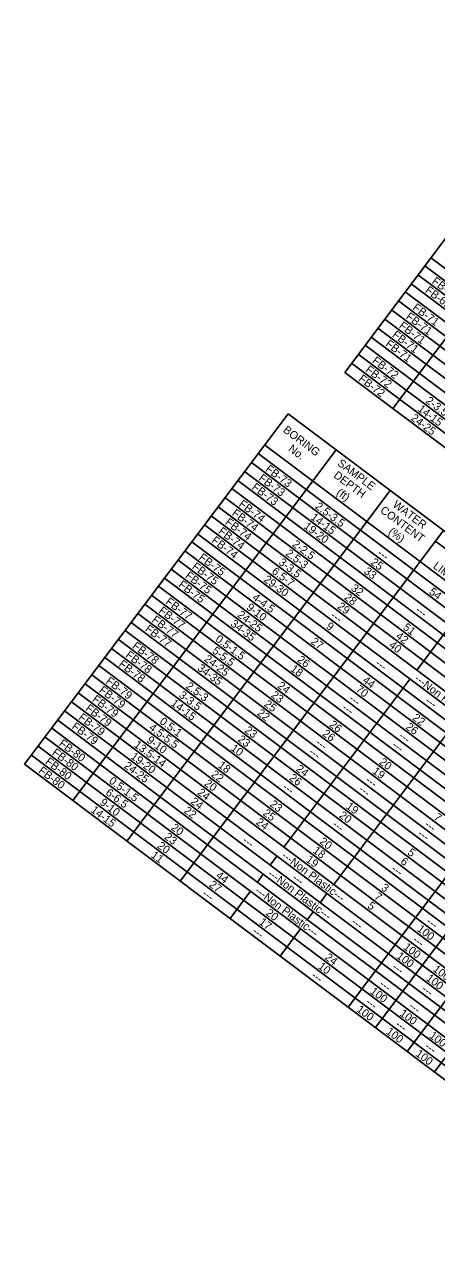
# Model space of a CAD drawing. Extents: x 627484.2 to 627514.4, y 367972.1 to 367996.9.
# Drawn here: x 627505.89 to 627508.72, y 367977.2 to 367985.65 of the extents above; entities that cross this region are included whole.
import ezdxf

# ---------------------------------------------------------------- set-up
doc = ezdxf.new("R2010")
doc.units = 0
doc.layers.add('Default', color=7, linetype='Continuous')
doc.layers.add('R_Survey Control', color=7, linetype='Continuous')

msp = doc.modelspace()

# ---------------------------------------------------------------- linework, layer by layer
at = {"layer": 'Default'}
for p, q in [((627508.0877, 367983.2583), (627509.8821, 367985.648)), ((627508.4191, 367983.0095), (627510.2135, 367985.3992)), ((627508.679, 367984.0458), (627513.1543, 367980.6853)), ((627508.5912, 367983.9289), (627513.0665, 367980.5684)), ((627508.638, 367983.9912), (627513.1133, 367980.6307)), ((627508.5444, 367983.8665), (627513.0196, 367980.506)), ((627508.4566, 367983.7495), (627512.9318, 367980.389)), ((627508.5034, 367983.8119), (627512.9786, 367980.4514)), ((627508.4097, 367983.6872), (627512.885, 367980.3267)), ((627508.3629, 367983.6248), (627512.8381, 367980.2643)), ((627508.2692, 367983.5), (627512.7445, 367980.1395)), ((627508.3161, 367983.5624), (627512.7913, 367980.2019)), ((627508.2282, 367983.4455), (627512.7035, 367980.085)), ((627508.1814, 367983.3831), (627512.6566, 367980.0226)), ((627508.0877, 367983.2583), (627512.563, 367979.8978)), ((627508.1346, 367983.3207), (627512.6098, 367979.9602)), ((627505.8895, 367980.5654), (627507.6986, 367982.9746)), ((627507.6986, 367982.9746), (627512.1738, 367979.6141)), ((627507.5376, 367982.7602), (627512.0128, 367979.3997)), ((627506.2209, 367980.3166), (627508.0299, 367982.7257)), ((627507.4937, 367982.7017), (627511.9689, 367979.3412)), ((627507.4, 367982.5769), (627511.8753, 367979.2164)), ((627507.4468, 367982.6393), (627511.9221, 367979.2788)), ((627507.3532, 367982.5146), (627511.8284, 367979.1541)), ((627506.5912, 367980.0385), (627508.4003, 367982.4477)), ((627507.2654, 367982.3976), (627511.7406, 367979.0371)), ((627507.3122, 367982.46), (627511.7874, 367979.0995)), ((627507.2185, 367982.3352), (627511.6938, 367978.9747)), ((627507.1717, 367982.2729), (627511.6469, 367978.9124)), ((627506.9577, 367979.7633), (627508.7667, 367982.1725)), ((627507.078, 367982.1481), (627511.5533, 367978.7876)), ((627507.1248, 367982.2105), (627511.6001, 367978.85)), ((627507.037, 367982.0936), (627511.5123, 367978.733)), ((627508.7111, 367982.0984), (627509.865, 367981.232)), ((627506.9902, 367982.0312), (627511.4654, 367978.6707)), ((627506.8965, 367981.9064), (627511.3718, 367978.5459)), ((627506.9434, 367981.9688), (627511.4186, 367978.6083)), ((627506.8497, 367981.8441), (627511.3249, 367978.4836)), ((627506.7619, 367981.7271), (627511.2371, 367978.3666)), ((627506.8087, 367981.7895), (627511.2839, 367978.429)), ((627506.715, 367981.6647), (627511.1903, 367978.3042)), ((627506.6682, 367981.6024), (627511.1434, 367978.2419)), ((627506.5804, 367981.4854), (627511.0556, 367978.1249)), ((627506.6214, 367981.54), (627511.0966, 367978.1795)), ((627508.5829, 367981.2132), (627508.8112, 367981.5173)), ((627506.5335, 367981.423), (627511.0088, 367978.0625)), ((627506.4399, 367981.2983), (627510.9151, 367977.9378)), ((627506.4867, 367981.3607), (627510.9619, 367978.0002)), ((627508.1116, 367978.8969), (627509.9206, 367981.306)), ((627506.3989, 367981.2437), (627510.8741, 367977.8832)), ((627506.352, 367981.1813), (627510.8273, 367977.8208)), ((627507.6696, 367979.9969), (627508.536, 367981.1508)), ((627506.2584, 367981.0566), (627510.7336, 367977.6961)), ((627506.3052, 367981.119), (627510.7805, 367977.7585)), ((627506.2115, 367980.9942), (627510.6868, 367977.6337)), ((627508.2987, 367978.7564), (627510.0024, 367981.0252)), ((627506.1647, 367980.9319), (627510.6399, 367977.5714)), ((627508.0126, 367979.7393), (627508.8791, 367980.8932)), ((627506.0769, 367980.8149), (627510.5521, 367977.4544)), ((627506.1179, 367980.8695), (627510.5931, 367977.509)), ((627508.517, 367978.5924), (627510.2207, 367980.8613)), ((627506.03, 367980.7525), (627510.5053, 367977.392)), ((627508.7041, 367978.4519), (627510.4078, 367980.7207)), ((627505.9364, 367980.6278), (627510.4116, 367977.2673)), ((627505.9832, 367980.6902), (627510.4585, 367977.3297)), ((627505.8895, 367980.5654), (627510.3648, 367977.2049)), ((627507.5759, 367979.8722), (627507.6227, 367979.9346)), ((627507.4881, 367979.7552), (627507.529, 367979.8098)), ((627507.3007, 367979.5057), (627507.4412, 367979.6929)), ((627507.9189, 367979.6146), (627507.9658, 367979.677)), ((627507.8311, 367979.4976), (627507.8721, 367979.5522)), ((627507.6438, 367979.2481), (627507.7843, 367979.4353))]:
    msp.add_line(p, q, dxfattribs=at)
at = {"layer": 'R_Survey Control'}
msp.add_line((627507.6986, 367982.9746), (627507.6986, 367982.9746), dxfattribs=at)

# ---------------------------------------------------------------- texts
at = {"layer": 'Default'}
for s, p in [('FB-69', (627508.6822, 367983.8749)), ('FB-69', (627508.6353, 367983.8126)), ('FB-71', (627508.5033, 367983.6313)), ('FB-71', (627508.5501, 367983.6937)), ('FB-71', (627508.4564, 367983.5689)), ('FB-71', (627508.4096, 367983.5066)), ('FB-71', (627508.3628, 367983.4442)), ('FB-72', (627508.2723, 367983.3292)), ('FB-72', (627508.1786, 367983.2045)), ('FB-72', (627508.2255, 367983.2668)), ('2-3.5', (627508.6393, 367983.0536)), ('14-15', (627508.5843, 367982.9974)), ('24-25', (627508.5375, 367982.935)), ('BORING', (627507.6604, 367982.8528)), ('No.', (627507.696, 367982.7229)), ('SAMPLE', (627508.0336, 367982.6241)), ('FB-73', (627507.4923, 367982.522)), ('FB-73', (627507.5391, 367982.5844)), ('DEPTH', (627508.0067, 367982.5412)), ('FB-73', (627507.4454, 367982.4597)), ('(ft)', (627508.0265, 367982.4231)), ('FB-74', (627507.3092, 367982.2815)), ('FB-74', (627507.356, 367982.3439)), ('2.5-3.5', (627507.8804, 367982.3281)), ('CONTENT', (627508.3268, 367982.3008)), ('WATER', (627508.4128, 367982.3394)), ('FB-74', (627507.2624, 367982.2192)), ('19-20', (627507.802, 367982.192)), ('14-15', (627507.8498, 367982.2536)), ('FB-74', (627507.2155, 367982.1568)), ('(%)', (627508.384, 367982.1546)), ('FB-74', (627507.1687, 367982.0944)), ('2-2.5', (627507.7233, 367982.0682)), ('FB-75', (627507.0819, 367981.9767)), ('3-3.5', (627507.6296, 367981.9434)), ('2.5-3', (627507.677, 367982.0054)), ('25', (627508.2615, 367981.9444)), ('---', (627508.3075, 367982.0074)), ('FB-75', (627506.9882, 367981.852)), ('FB-75', (627507.0351, 367981.9143)), ('6.5-7', (627507.5821, 367981.8816)), ('33', (627508.2152, 367981.8816)), ('LIMIT', (627508.6904, 367981.9183)), ('FB-75', (627506.9414, 367981.7896)), ('29-30', (627507.5268, 367981.8255)), ('32', (627508.126, 367981.7657)), ('4-4.5', (627507.4481, 367981.7017)), ('28', (627508.0797, 367981.703)), ('54', (627508.662, 367981.7412)), ('FB-77', (627506.806, 367981.6108)), ('FB-77', (627506.8529, 367981.6731)), ('9-10', (627507.4084, 367981.634)), ('29', (627508.0324, 367981.6409)), ('---', (627508.5686, 367981.6163)), ('FB-77', (627506.7592, 367981.5484)), ('34-35', (627507.2994, 367981.5207)), ('24-25', (627507.3463, 367981.5831)), ('---', (627507.9855, 367981.5786)), ('FB-77', (627506.7124, 367981.486)), ('9', (627507.955, 367981.504)), ('42', (627508.4339, 367981.437)), ('51', (627508.4834, 367981.4973)), ('FB-78', (627506.625, 367981.3688)), ('0.5-1.5', (627507.1954, 367981.4159)), ('27', (627507.851, 367981.3992)), ('40', (627508.3869, 367981.3747)), ('FB-78', (627506.5781, 367981.3064)), ('24-25', (627507.118, 367981.279)), ('5-5.5', (627507.1729, 367981.3353)), ('26', (627507.7571, 367981.2746)), ('FB-78', (627506.5313, 367981.244)), ('34-35', (627507.0711, 367981.2166)), ('18', (627507.7109, 367981.2118)), ('---', (627508.2934, 367981.2499)), ('FB-79', (627506.443, 367981.1274)), ('2.5-3', (627506.992, 367981.0932)), ('24', (627507.6223, 367981.0954)), ('44', (627508.2054, 367981.1331)), ('---Non Plastic---', (627508.5625, 367981.1453)), ('FB-79', (627506.3493, 367981.0027)), ('FB-79', (627506.3962, 367981.0651)), ('3-3.5', (627506.9446, 367981.0312)), ('23', (627507.5771, 367981.0318)), ('70', (627508.1586, 367981.0707)), ('FB-79', (627506.3025, 367980.9403)), ('14-15', (627506.8896, 367980.9749)), ('25', (627507.5297, 367980.9699)), ('---', (627508.0651, 367980.9458)), ('---', (627508.1119, 367981.0082)), ('---', (627508.6364, 367980.9923)), ('FB-79', (627506.2556, 367980.8779)), ('0.5-1', (627506.8118, 367980.8505)), ('22', (627507.482, 367980.9081)), ('22', (627508.5487, 367980.8753)), ('FB-79', (627506.2088, 367980.8156)), ('4.5-5.5', (627506.7387, 367980.8078)), ('23', (627507.3956, 367980.7901)), ('26', (627507.9303, 367980.7665)), ('26', (627507.9772, 367980.8289)), ('26', (627508.5017, 367980.813)), ('FB-80', (627506.1208, 367980.6988)), ('13.5-14', (627506.6359, 367980.6899)), ('9-10', (627506.7234, 367980.7218)), ('23', (627507.3487, 367980.7277)), ('---', (627507.8836, 367980.7041)), ('---', (627508.4081, 367980.6882)), ('---', (627508.455, 367980.7506)), ('FB-80', (627506.0739, 367980.6364)), ('19-20', (627506.6135, 367980.6092)), ('10', (627507.3003, 367980.6665)), ('---', (627507.8367, 367980.6417)), ('FB-80', (627505.9803, 367980.5117)), ('FB-80', (627506.0271, 367980.5741)), ('24-25', (627506.5676, 367980.5461)), ('18', (627507.2132, 367980.5491)), ('24', (627507.7487, 367980.5249)), ('19', (627508.2735, 367980.5088)), ('20', (627508.3201, 367980.5714)), ('0.5-1.5', (627506.4636, 367980.4414)), ('20', (627507.1189, 367980.4248)), ('22', (627507.1659, 367980.4871)), ('26', (627507.702, 367980.4625)), ('---', (627508.2266, 367980.4465)), ('6-6.5', (627506.4411, 367980.3607)), ('24', (627507.072, 367980.3625)), ('---', (627507.6553, 367980.4)), ('---', (627508.1798, 367980.3841)), ('9-10', (627506.4014, 367980.293)), ('24', (627507.0252, 367980.3001)), ('23', (627507.5688, 367980.282)), ('19', (627508.092, 367980.2671)), ('14-15', (627506.3393, 367980.2421)), ('22', (627506.9785, 367980.2376)), ('25', (627507.5214, 367980.2201)), ('20', (627508.045, 367980.2049)), ('7', (627508.6953, 367980.1921)), ('20', (627506.8905, 367980.1208)), ('24', (627507.4736, 367980.1585)), ('---', (627507.9983, 367980.1424)), ('---', (627508.6321, 367980.1421)), ('20', (627506.7969, 367979.996)), ('23', (627506.8452, 367980.0572)), ('---', (627507.3801, 367980.0336)), ('20', (627507.9103, 367980.0256)), ('---', (627508.5852, 367980.0797)), ('11', (627506.7528, 367979.9315)), ('---Non Plastic---', (627507.6492, 367979.9291)), ('18', (627507.8642, 367979.9627)), ('5', (627508.5145, 367979.9499)), ('19', (627507.8169, 367979.9007)), ('6', (627508.4667, 367979.8882)), ('44', (627507.1984, 367979.792)), ('---Non Plastic---', (627507.5555, 367979.8043)), ('---', (627507.7231, 367979.776)), ('---', (627508.4037, 367979.838)), ('27', (627507.1519, 367979.7294)), ('---Non Plastic---', (627507.4677, 367979.6874)), ('3', (627508.3335, 367979.7078)), ('---', (627507.1049, 367979.6672)), ('5', (627508.2393, 367979.5835)), ('7', (627508.2855, 367979.6464)), ('20', (627507.5415, 367979.5344)), ('17', (627507.495, 367979.4718)), ('---', (627508.1286, 367979.4716)), ('100', (627508.5801, 367979.4251)), ('---', (627508.6434, 367979.4752)), ('---', (627507.448, 367979.4096)), ('---', (627508.5497, 367979.3504)), ('100', (627508.4396, 367979.238)), ('100', (627508.4865, 367979.3004)), ('10', (627507.9001, 367979.1676)), ('24', (627507.9469, 367979.23)), ('---', (627507.8534, 367979.1051)), ('---', (627508.4092, 367979.1633)), ('100', (627508.6423, 367979.0858)), ('100', (627508.6892, 367979.1481)), ('100', (627508.2581, 367978.9963)), ('---', (627508.3214, 367979.0463)), ('---', (627508.6119, 367979.0111)), ('---', (627508.2277, 367978.9216)), ('100', (627508.1645, 367978.8715)), ('100', (627508.4608, 367978.8441)), ('---', (627508.5241, 367978.8941)), ('---', (627508.4304, 367978.7694)), ('100', (627508.3672, 367978.7193)), ('100', (627508.6635, 367978.6919)), ('100', (627508.5699, 367978.5671)), ('---', (627508.6331, 367978.6172))]:
    msp.add_text(s, height=0.055, rotation=323.09678, dxfattribs=at).set_placement(p)

doc.saveas('drawing.dxf')
